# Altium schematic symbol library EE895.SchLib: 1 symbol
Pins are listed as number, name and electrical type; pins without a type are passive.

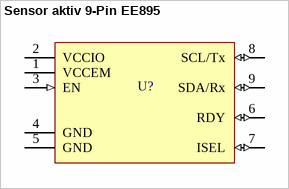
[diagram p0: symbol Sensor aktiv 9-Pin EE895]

## Sensor aktiv 9-Pin EE895
designator U?  (value not drawn)
Sensor, aktiv, 9-Pin, Basis: EE895 (E+E)
pins: 1 VCCEM (power), 2 VCCIO (power), 3 EN (in), 4 GND (power), 5 GND (power), 6 RDY (io), 7 ISEL (io), 8 SCL/Tx (io), 9 SDA/Rx (io)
